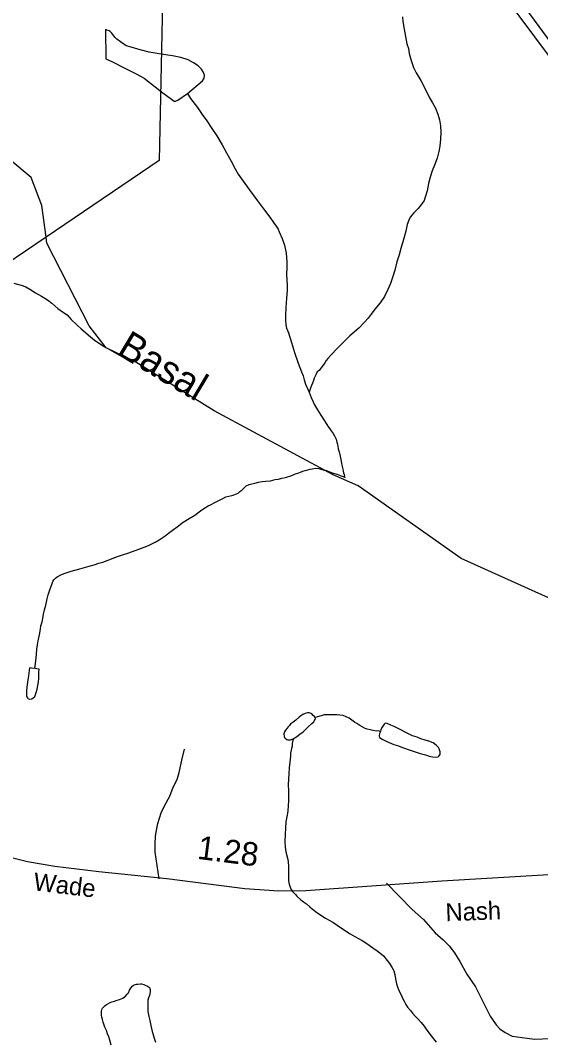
# Model space of a CAD drawing. Extents: x 2001466 to 2224147, y 644118 to 847247.
# Drawn here: x 2049275 to 2052052, y 678885 to 684326 of the extents above; entities that cross this region are included whole.
import ezdxf

# ---------------------------------------------------------------- set-up
doc = ezdxf.new("R2010")
doc.units = 0
for name, color, linetype in [('Exist Hydrographic Creek Single Shore', 7, 'Continuous'), ('Exist Hydrographic Creek Single Shore Label', 7, 'Continuous'), ('Exist Hydrographic Misc Water Feature', 7, 'Continuous'), ('Exist Road Non-System Type 51', 7, 'Continuous'), ('Exist Road Primary NC Divided Attributed', 7, 'Continuous'), ('Exist Road Secondary Mileage Hundredths English Label', 7, 'Continuous'), ('Exist Road Secondary Type 51 Attributed', 7, 'Continuous'), ('Exist Road Secondary Type 51 Label', 7, 'Continuous'), ('Exist Utilities Electrical Transmission Line', 7, 'Continuous')]:
    doc.layers.add(name, color=color, linetype=linetype)

msp = doc.modelspace()

# ---------------------------------------------------------------- linework, layer by layer
at = {"layer": 'Exist Hydrographic Creek Single Shore'}
for points in [[(2049411.6, 683170), (2049389.8, 683338.3), (2049331.9, 683487.2), (2049222.9, 683577.9), (2048680.9, 683828.5), (2048479.9, 684118), (2048444.7, 684220.5)], [(2049891.7, 682502.8), (2049732.8, 682580), (2049641.8, 682696.8), (2049415.8, 683137.7), (2049411.6, 683170)], [(2050943.9, 681902.5), (2050309.8, 682243.5), (2049891.7, 682502.8)], [(2054019.6, 681016.4), (2053770.7, 680942.8), (2053578.8, 680959.8), (2053269.8, 681015.3), (2052861.7, 681033.5), (2052094.8, 681245.9), (2051627.7, 681455.5), (2051077.8, 681844.1), (2050943.9, 681902.5)]]:
    msp.add_lwpolyline(points, dxfattribs=at)
at = {"layer": 'Exist Hydrographic Misc Water Feature'}
for points in [[(2051314.4, 684345.8), (2051316.4, 684319.9), (2051322.6, 684280), (2051330.4, 684239.9), (2051338.4, 684201.8), (2051346.4, 684175.9), (2051350.7, 684150.1), (2051360.3, 684112), (2051372.8, 684074.1), (2051386.8, 684046), (2051412.8, 684005.9), (2051436.8, 683958.1), (2051458.9, 683912.2), (2051475.4, 683886.1), (2051491.1, 683858.2), (2051503.2, 683826.3), (2051511.4, 683796.3), (2051517, 683764.2), (2051519, 683730.2), (2051517.4, 683692.4), (2051513.7, 683654.4), (2051507.7, 683626.1), (2051499.5, 683590.4), (2051485.6, 683554.4), (2051473.7, 683524.2), (2051461.6, 683490.3), (2051453.8, 683456.2), (2051445.8, 683416.4), (2051437.8, 683388.5), (2051429.8, 683366.2), (2051417.9, 683348.1), (2051397.8, 683322.3), (2051375.9, 683300.1), (2051356.2, 683276.3), (2051348, 683260.1), (2051340.2, 683238.2), (2051332.4, 683202.1), (2051320.3, 683158.1), (2051306.4, 683109.9), (2051296.5, 683076.1), (2051284.7, 683038.1), (2051272.8, 682994.1), (2051262.7, 682960), (2051250.8, 682922), (2051237.1, 682890), (2051218.6, 682853.9), (2051195, 682819.7), (2051167, 682785.9), (2051147.3, 682759.6), (2051131.3, 682737.7), (2051111.4, 682715.6), (2051081, 682683.7), (2051033.5, 682643.5), (2050965.6, 682575.4), (2050933.6, 682541.4), (2050915.4, 682523.4), (2050907.4, 682511.3), (2050899.4, 682499.1)], [(2050167.3, 683935.6), (2050247.1, 684003.9), (2050254.9, 684017.7), (2050257.1, 684034), (2050250.8, 684052), (2050240.7, 684066.1), (2050222.9, 684083.8), (2050198.9, 684099.6), (2050170.8, 684115.6), (2050130.8, 684127.8), (2050086.9, 684137.7), (2050026.7, 684145.6), (2049962.7, 684157.3), (2049914.5, 684169.1), (2049866.7, 684183.2), (2049838.8, 684191.1), (2049826.9, 684199), (2049808.5, 684211.1), (2049788.8, 684225.1), (2049780.6, 684234.8), (2049773, 684242.9), (2049762.6, 684257), (2049754.6, 684266.7), (2049748.8, 684270.8), (2049736.7, 684274.7), (2049728.5, 684276.8), (2049731, 684120.6), (2049767.1, 684105.1), (2049832.7, 684071.1), (2049892.8, 684041.3), (2049915.1, 684029), (2049935.2, 684017.5), (2050027.3, 683945.5), (2050081, 683905.8), (2050095.1, 683895.5), (2050103.1, 683895.5), (2050115.2, 683899.7), (2050167.3, 683935.6)], [(2050167.3, 683935.6), (2050183.3, 683909.7), (2050219.4, 683861.6), (2050245, 683824.1), (2050269.6, 683790), (2050297.3, 683750), (2050323.4, 683710), (2050351.7, 683662.3), (2050375.7, 683620.1), (2050399.9, 683574.3), (2050421.6, 683534.5), (2050437.8, 683506.5), (2050464.2, 683468.4), (2050496, 683424.2), (2050539.9, 683364.4), (2050572.3, 683320.6), (2050606.5, 683276.4), (2050626, 683248.7), (2050640.2, 683228.8), (2050650.2, 683212.6), (2050656.4, 683198.7), (2050672.6, 683162.6), (2050684.9, 683126.7), (2050692.7, 683084.9), (2050697, 683038.8), (2050696.8, 683006.9), (2050694.9, 682973), (2050697.2, 682943.1), (2050698.8, 682912.8), (2050698.8, 682884.8), (2050695.1, 682844.8), (2050691.2, 682795.1), (2050689.2, 682752.8), (2050689.6, 682726.9), (2050691.6, 682703), (2050695.3, 682685), (2050705.4, 682659.1), (2050721.6, 682607.2), (2050737.4, 682554.9), (2050757.5, 682498.7)], [(2049239.5, 682924), (2049279, 682914.4), (2049303.2, 682904.2), (2049325.6, 682892.3), (2049355.3, 682872.4), (2049387.3, 682854.6), (2049419.1, 682836.4), (2049441.6, 682818.4), (2049475.3, 682788.5), (2049505.6, 682768.5), (2049523.7, 682754.8), (2049545.6, 682730.8), (2049575.3, 682702.8), (2049599.7, 682680.8), (2049621.5, 682660.9), (2049649.8, 682637.1), (2049675.8, 682617), (2049715.6, 682591)], [(2049715.6, 682591), (2049725.6, 682585), (2049787.8, 682549.2), (2049831.9, 682525.1), (2049877.2, 682497.1)], [(2050757.5, 682498.7), (2050775.3, 682451), (2050783.5, 682431.1), (2050789.7, 682409.1), (2050797.4, 682385.2), (2050807.5, 682363), (2050815.5, 682343.1)], [(2050899.4, 682499.1), (2050869.4, 682459.1), (2050859.6, 682451.2), (2050851.4, 682435), (2050843.2, 682417.2), (2050839.5, 682405.2), (2050833.3, 682391.1), (2050829.6, 682379.1), (2050825.5, 682369.2), (2050819.8, 682353), (2050815.5, 682343.1)], [(2050815.5, 682343.1), (2050827.4, 682314.9), (2050837.4, 682291.1), (2050845.4, 682275.3), (2050861.6, 682249.3), (2050877.8, 682221.3), (2050893.8, 682195.4), (2050909.8, 682171), (2050919.9, 682157.3), (2050926.2, 682147.4), (2050933.8, 682137.3), (2050943.9, 682123.3), (2050951.9, 682109.5), (2050959.6, 682093.3), (2050963.7, 682077.3), (2050968.3, 682065.2), (2050969.9, 682055.2), (2050971.9, 682041.5), (2050976, 682025.5), (2050980.2, 682011.5), (2050984.3, 681993.4), (2050986.1, 681983.4), (2050988.1, 681965.3), (2050990.4, 681953.6), (2050996.6, 681931.6), (2050998.2, 681921.6), (2051000.2, 681913.5), (2051002.5, 681903.5), (2051004.6, 681895.5), (2051002.1, 681891.4), (2051008.2, 681887.6)], [(2049350.8, 680868.6), (2049356.5, 680910.7), (2049358.4, 680926.7), (2049360.4, 680946.6), (2049362.1, 680972.7), (2049366.2, 680994.8), (2049369.9, 681016.6), (2049376, 681048.5), (2049382.4, 681078.8), (2049384, 681096.7), (2049390, 681118.6), (2049394.1, 681136.6), (2049397.8, 681158.8), (2049403.9, 681182.6), (2049409.7, 681206.9), (2049417.9, 681240.5), (2049423.6, 681262.7), (2049431.4, 681288.7), (2049443.9, 681322.6), (2049447.6, 681332.5), (2049453.5, 681342.6), (2049461.7, 681350.7), (2049471.6, 681358.9), (2049493.5, 681370.6), (2049519.6, 681378.8), (2049545.4, 681389), (2049591.7, 681401.1), (2049641.2, 681415.1), (2049669.3, 681423), (2049693.7, 681431.1), (2049715.4, 681437.1), (2049793.1, 681467.5), (2049819.6, 681475.3), (2049853.2, 681485.6), (2049907.5, 681505.3), (2049935.2, 681515.7), (2049959.2, 681525.5), (2049993.4, 681543.8), (2050015.2, 681555.5), (2050031, 681565.7), (2050047, 681577.8), (2050065, 681591.7), (2050085.3, 681605.7), (2050119.1, 681629.8), (2050138.8, 681645.9), (2050166.9, 681663.9), (2050206.5, 681687.9), (2050237, 681710.1), (2050254.7, 681722), (2050276.6, 681736.1), (2050288.7, 681742), (2050316.6, 681756.4), (2050354.7, 681776.2), (2050370.9, 681784.3), (2050386.9, 681788.3), (2050410.9, 681794.4), (2050436.4, 681804.4), (2050446.6, 681812.5), (2050456.4, 681820.4), (2050468.5, 681832.3), (2050480.6, 681842.7), (2050496.2, 681850.4), (2050510.6, 681854.8), (2050526.6, 681858.4), (2050546.5, 681862.7), (2050564.5, 681866.9), (2050584.4, 681868.7), (2050610.6, 681870.8), (2050634.6, 681876.9), (2050652.3, 681878.7), (2050670.3, 681884.9), (2050690.6, 681888.7), (2050724.5, 681899), (2050738.4, 681905), (2050760.5, 681913), (2050770.6, 681917.2), (2050782.3, 681921.1), (2050794.4, 681925.3), (2050808.3, 681929.3), (2050822.1, 681933.3), (2050832.1, 681935), (2050852, 681937.2), (2050868.4, 681935.2), (2050884.2, 681931.2), (2050896.3, 681927.3), (2050909.4, 681925.3), (2050916.6, 681921.4)], [(2050916.6, 681921.4), (2050930.3, 681917.3), (2050944.3, 681911.5), (2050958, 681907.4), (2050970.1, 681903.5), (2050982.2, 681899.3), (2050992, 681895.3), (2051002.1, 681891.4), (2051008.2, 681887.6)], [(2049350.8, 680868.6), (2049334.6, 680870.6), (2049322.5, 680872.5), (2049318.4, 680830.5), (2049314.9, 680808.7), (2049310.8, 680784.6), (2049308.6, 680768.7), (2049306.7, 680752.4), (2049306.7, 680742.6), (2049306.7, 680732.5), (2049306.7, 680724.4), (2049308.8, 680718.4), (2049312.9, 680712.5), (2049314.7, 680708.6), (2049322.9, 680706.5), (2049334.8, 680706.7), (2049342.6, 680712.8), (2049350.8, 680720.5), (2049358.8, 680740.8), (2049364.7, 680758.6), (2049368.4, 680778.7), (2049370.5, 680798.7), (2049372.7, 680816.6), (2049372.5, 680830.8), (2049372.3, 680842.6), (2049372.7, 680852.7), (2049374.4, 680862.6), (2049374.6, 680866.6), (2049362.3, 680866.8), (2049350.8, 680868.6)], [(2050848.9, 680607.3), (2050842.6, 680615.6), (2050838.5, 680619.4), (2050830.5, 680627.5), (2050826.6, 680629.4), (2050816.5, 680633.3), (2050806.9, 680633.2), (2050794.8, 680629.3), (2050782.7, 680623.4), (2050772.6, 680617.3), (2050762.4, 680609.1), (2050745, 680593.1), (2050729, 680581.3), (2050718.5, 680575.2), (2050710.9, 680565), (2050704.8, 680559), (2050698.8, 680551), (2050690.8, 680541.3), (2050684.9, 680531.2), (2050680.6, 680521.3), (2050683, 680507.2), (2050684.9, 680501.2), (2050689, 680497.3), (2050697, 680491.3), (2050702.9, 680489.1), (2050716.9, 680489), (2050730.6, 680495.1)], [(2050730.6, 680495.1), (2050739, 680499.1), (2050750.9, 680507.4), (2050766.9, 680519.2), (2050784.7, 680531.5), (2050797, 680543.4), (2050810.8, 680557.6), (2050830.9, 680575.6), (2050840.5, 680585.5), (2050844.8, 680591.3), (2050848.9, 680597.6), (2050850.4, 680601.4), (2050848.9, 680607.3)], [(2051196.7, 680533.9), (2051186.8, 680536.2), (2051174.9, 680536), (2051156.5, 680538), (2051142.8, 680542.1), (2051126.8, 680545.7), (2051114.7, 680550), (2051103, 680555.8), (2051086.8, 680566), (2051070.6, 680575.8), (2051058.7, 680583.6), (2051044.7, 680593.9), (2051030.6, 680603.7), (2051014.6, 680611.8), (2050998.6, 680617.9), (2050980.6, 680619.8), (2050966.4, 680621.5), (2050956.6, 680621.8), (2050948.6, 680621.8), (2050932.4, 680621.4), (2050914.5, 680621.7), (2050896.7, 680621.6), (2050880.7, 680617.5), (2050860.6, 680611.6), (2050848.9, 680607.3)], [(2051196.7, 680533.9), (2051190.9, 680522.2), (2051190.5, 680508), (2051192.6, 680502.1), (2051209, 680490.3), (2051230.9, 680480.1), (2051268.7, 680464.2), (2051292.9, 680456.4), (2051315, 680448.2), (2051354.8, 680434.5), (2051386.8, 680422.3), (2051409.1, 680416.5), (2051436.8, 680408.7), (2051456.9, 680402.4), (2051474.9, 680398.8), (2051490.9, 680396.8), (2051504.7, 680398.7), (2051508.8, 680402.6), (2051514.9, 680410.6), (2051515.1, 680424.8), (2051511, 680440.8), (2051506.7, 680448.8), (2051494.6, 680460.7), (2051478.8, 680472.5), (2051454.6, 680482.6), (2051434.8, 680486.5), (2051412.8, 680494.7), (2051392.9, 680502.6), (2051368.7, 680510.2), (2051324.6, 680532.3), (2051308.6, 680540.4), (2051288.5, 680550.4), (2051270.7, 680560), (2051252.5, 680568), (2051232.6, 680575.9), (2051226.4, 680578.1), (2051220.7, 680576.1), (2051216.6, 680572.3), (2051206.7, 680556.3), (2051198.7, 680544.1), (2051196.7, 680533.9)], [(2050730.6, 680495.1), (2050729, 680485.2), (2050725.1, 680469.1), (2050724.9, 680455.4), (2050722.8, 680443.1), (2050720.8, 680433.3), (2050717.3, 680417.2), (2050717.3, 680401.4), (2050713.2, 680369.2), (2050708.9, 680339.3), (2050707.4, 680307.1), (2050705.2, 680281.1), (2050703.3, 680247.3), (2050705.4, 680219), (2050705.8, 680185.3), (2050705.6, 680163), (2050703.7, 680139.4), (2050701.7, 680109.3), (2050697.4, 680079.1), (2050691.4, 680051.2), (2050689.8, 680017.4), (2050687.7, 679985.3), (2050685.7, 679945.4), (2050688, 679917.1), (2050692.1, 679891.3), (2050700, 679857.3), (2050704.1, 679839.2), (2050706, 679811.3), (2050706.2, 679785.3), (2050706.2, 679761.4), (2050706.4, 679737.4), (2050710.1, 679719.4), (2050714.2, 679703.4), (2050720.3, 679691.5), (2050726.3, 679681.3), (2050734.5, 679673.5), (2050742.5, 679663.4), (2050750.1, 679655.4), (2050772.2, 679635.4), (2050786.4, 679625.5), (2050802.2, 679613.4), (2050820.4, 679597.7), (2050832.7, 679587.7), (2050850.4, 679573.6), (2050878.4, 679553.6), (2050902.6, 679537.7), (2050942.8, 679515.8), (2050966.4, 679500.1), (2050999, 679478.1), (2051034.9, 679454), (2051060.5, 679439.9), (2051098.5, 679418), (2051124.9, 679402.2), (2051156.9, 679380.3), (2051184.6, 679360.3), (2051212.9, 679336.1), (2051233.2, 679312.4), (2051244.9, 679296.4), (2051257, 679276.3), (2051265.2, 679264.6), (2051268.9, 679256.2), (2051273.2, 679236.6), (2051277.1, 679214.5), (2051283, 679188.4), (2051289.2, 679166.4), (2051297.2, 679148.5), (2051307, 679128.4), (2051315.4, 679110.5), (2051323.4, 679094.7), (2051333.2, 679076.6), (2051341, 679062.8), (2051357.2, 679044.5), (2051367.7, 679030.8), (2051381.6, 679014.9), (2051397.6, 678998.7), (2051413.4, 678980.9), (2051429.6, 678961), (2051441.3, 678945), (2051455.9, 678927), (2051467.6, 678911), (2051479.9, 678894.9), (2051493.8, 678877)], [(2049759.7, 678859.7), (2049752.1, 678887.6), (2049746.1, 678905.6), (2049739.8, 678921.5), (2049733.8, 678939.4), (2049726.1, 678955.6), (2049721.5, 678967.7), (2049715.8, 678983.6), (2049712.1, 678997.5), (2049709.4, 679009.7), (2049707.8, 679019.7), (2049708, 679031.4), (2049707.6, 679039.6), (2049709.9, 679049.8), (2049711.7, 679053.6), (2049713.5, 679057.7), (2049719.7, 679065.7), (2049725.8, 679069.7), (2049733.6, 679077.8), (2049741.4, 679081.5), (2049753.5, 679087.7), (2049763.6, 679091.5), (2049777.3, 679095.9), (2049791.7, 679099.8), (2049803.4, 679103.7), (2049821.6, 679111.9), (2049835.8, 679121.9), (2049843.8, 679131.7), (2049851.3, 679139.8), (2049857.7, 679153.9), (2049863.4, 679164), (2049871.4, 679175.7), (2049881.5, 679181.9), (2049893.6, 679185.8), (2049901.2, 679185.8), (2049915.1, 679188.2), (2049921.1, 679188.1), (2049933.2, 679183.8), (2049941.6, 679180.1), (2049953.5, 679175.9), (2049959.2, 679172.1), (2049963.7, 679167.8), (2049967.6, 679157.9), (2049967.4, 679151.9), (2049967.4, 679144.1), (2049963.5, 679126.1), (2049959.4, 679112.1), (2049955.3, 679100.2), (2049955.5, 679088), (2049955.3, 679072.2), (2049955.7, 679055.9), (2049955.5, 679040.1), (2049959.6, 679013.9), (2049965.8, 678991.9), (2049970.1, 678966.1), (2049977.9, 678934.1), (2049981.8, 678922.1), (2049987.9, 678898.1), (2049995.7, 678876.2)]]:
    msp.add_lwpolyline(points, dxfattribs=at)
at = {"layer": 'Exist Road Non-System Type 51'}
for points in [[(2050014.7, 679747.1), (2049993.6, 679889.6), (2049994.6, 679937.5), (2049995.3, 679971.5), (2049997.6, 679987.5), (2050008.8, 680043.3), (2050025.9, 680098.9), (2050044.7, 680136.5), (2050071.7, 680188), (2050090.7, 680235.6), (2050111.5, 680277.2), (2050122.3, 680315), (2050135.6, 680380.7), (2050150.8, 680438.4)], [(2051228.3, 679724.5), (2051365.4, 679583.7), (2051426.3, 679530.5), (2051488.9, 679459.2), (2051532.1, 679422.3), (2051563.4, 679389.7), (2051592.7, 679353.1), (2051619.8, 679306.5), (2051658.4, 679239.8), (2051705, 679170.8), (2051745.3, 679090), (2051781.8, 679015.2), (2051814.9, 678968.6), (2051834.5, 678948.2), (2051862, 678927.6), (2051899.7, 678908.8), (2051953.5, 678901.8), (2052019.3, 678892.4), (2052145.4, 678897.9)]]:
    msp.add_lwpolyline(points, dxfattribs=at)
at = {"layer": 'Exist Road Primary NC Divided Attributed'}
for points in [[(2052762.7, 683375.1), (2052719.2, 683428.3), (2052582.6, 683603.6), (2052303.7, 683957.8), (2052138.7, 684165.1), (2051970.2, 684395.2), (2051742, 684704.9), (2051573.5, 684938.4), (2051436.2, 685140.7), (2051333.9, 685293.7), (2051228.8, 685448.1)], [(2052731.9, 683324.9), (2052440.3, 683693.6), (2052263.9, 683918), (2052098.9, 684133.2), (2051937.2, 684349.6), (2051713, 684650.3), (2051549.1, 684880.3), (2051393.1, 685102.4), (2051275.9, 685268.7), (2051180.3, 685414.4)]]:
    msp.add_lwpolyline(points, dxfattribs=at)
at = {"layer": 'Exist Road Secondary Type 51 Attributed'}
msp.add_lwpolyline([(2054499.7, 679701.2), (2054403, 679730.5), (2054309.2, 679755.5), (2054093.7, 679812.7), (2053794.5, 679886.6), (2053662.5, 679901.4), (2053495.8, 679903.5), (2053047.7, 679908.8), (2052867.2, 679908.8), (2052742.6, 679901.4), (2052537.3, 679847.5), (2052277.6, 679798.9), (2052096, 679769.3), (2051525, 679734.5), (2050798.2, 679682.7), (2050653.6, 679681.7), (2050473.1, 679694.3), (2050055.6, 679748.2), (2049693.5, 679785.2), (2049458.1, 679813.7), (2049313, 679838), (2049147.3, 679879.2)], dxfattribs=at)
at = {"layer": 'Exist Utilities Electrical Transmission Line'}
for points in [[(2050172.3, 685300), (2050048.4, 685190.1), (2050014.9, 683578.4), (2049411.6, 683170)], [(2049411.6, 683170), (2048434, 682508.2), (2048472, 681708.3)]]:
    msp.add_lwpolyline(points, dxfattribs=at)

# ---------------------------------------------------------------- texts
at = {"layer": 'Exist Hydrographic Creek Single Shore Label'}
msp.add_text('Basal', height=150, rotation=329.0641, dxfattribs=at).set_placement((2049783.1, 682549.1))
at = {"layer": 'Exist Road Secondary Mileage Hundredths English Label'}
msp.add_text('1.28', height=125, rotation=352.6472, dxfattribs=at).set_placement((2050214.9, 679854.8))
at = {"layer": 'Exist Road Secondary Type 51 Label'}
for s, rotation, p in [('Wade', 353.2205, (2049340.7, 679686.6)), ('Nash', 2.2032, (2051545.8, 679521.2))]:
    msp.add_text(s, height=95, rotation=rotation, dxfattribs=at).set_placement(p)

doc.saveas('drawing.dxf')
